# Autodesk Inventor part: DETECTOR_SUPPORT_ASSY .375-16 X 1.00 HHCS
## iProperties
Shininess: 64.0
Length Units: 11272
Angle Units: 11279
Time Units: 11290
Mass Units: 11286
Length Display Precision: 3
Angle Display Precision: 2
Compacted: True
Part Number: DETECTOR_SUPPORT_ASSY .375-16 X 1.00 HHCS
Document SubType Name: Modeling
Created: 2004-08
Designer: John Blackburn
Material: STAINLESS_STEEL, AUSTENITIC
Manufacturer: Standard
Standards Organization: Custom
Density: 0.0
Volumn: 0.0
Area: 0.0
PropertySet Name: Model Information
Control State: 0
Master: False
Checked Out: False
Author: John Blackburn
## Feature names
1. Base1
